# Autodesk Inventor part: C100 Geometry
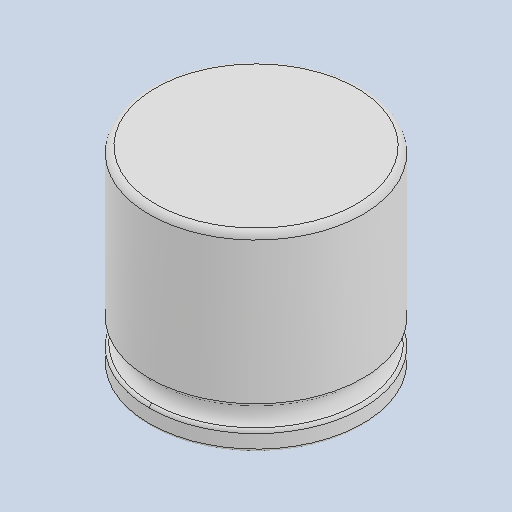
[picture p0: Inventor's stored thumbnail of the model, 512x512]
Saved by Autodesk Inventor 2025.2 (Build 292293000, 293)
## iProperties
Created: 2025-04
Part Number: C100 Geometry
Material: Generic
Description: PART-C100 Geometry-DESC
Document SubType Name: Modeling
Designer: BennF
Density: 1 g/cm^3
Appearance: Default
Author: BennF
Revision Number: NONE
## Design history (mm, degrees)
feature "Solid"
body "Solid1"
